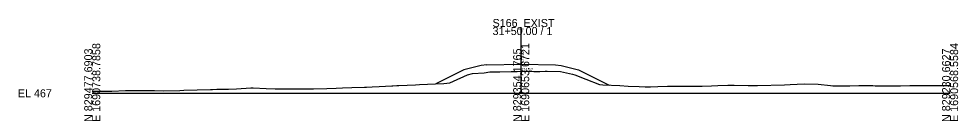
# Model space of a CAD drawing. Extents: x 1621104 to 1621433, y 1192880 to 1199414.
# Drawn here: x 1621104.2 to 1621432.7, y 1196879.5 to 1196915.2 of the extents above; entities that cross this region are included whole.
import ezdxf

# ---------------------------------------------------------------- set-up
doc = ezdxf.new("R2010")
doc.units = 0
for name, color, linetype in [('RD_GPK_XS_Cell', 7, 'Continuous'), ('RD_XS_EarthShd', 7, 'Continuous'), ('RD_XS_ExGround', 7, 'Continuous'), ('RD_XS_Pave', 7, 'Continuous'), ('RD_XS_TieSlope', 7, 'Continuous'), ('RD_XS_TX_Elev_EX', 7, 'Continuous'), ('RD_XS_TX_Elev_PR', 7, 'Continuous')]:
    doc.layers.add(name, color=color, linetype=linetype)

msp = doc.modelspace()

# ---------------------------------------------------------------- linework, layer by layer
at = {"layer": 'RD_GPK_XS_Cell'}
for p, q in [((1621279.86, 1196889.24), (1621279.86, 1196912.33)), ((1621129.86, 1196889.24), (1621279.86, 1196889.24)), ((1621279.86, 1196889.24), (1621429.86, 1196889.24))]:
    msp.add_line(p, q, dxfattribs=at)
at = {"layer": 'RD_XS_EarthShd'}
for p, q in [((1621267.86, 1196899.12), (1621265.86, 1196898.96)), ((1621291.86, 1196899.12), (1621293.86, 1196898.96))]:
    msp.add_line(p, q, dxfattribs=at)
at = {"layer": 'RD_XS_ExGround'}
msp.add_lwpolyline([(1621129.86, 1196890.01), (1621131.68, 1196889.97), (1621134.86, 1196889.97), (1621136.68, 1196890.04), (1621141.53, 1196890.17), (1621146.31, 1196890.19), (1621148.64, 1196890.17), (1621151.6, 1196890.17), (1621154.62, 1196890.09), (1621160.5, 1196890.27), (1621161.83, 1196890.35), (1621171.16, 1196890.6), (1621171.92, 1196890.62), (1621173.45, 1196890.65), (1621177.46, 1196890.7), (1621180.28, 1196890.84), (1621185.31, 1196891.14), (1621186.08, 1196891.15), (1621190.67, 1196890.87), (1621193.78, 1196890.82), (1621196.17, 1196890.81), (1621199.73, 1196890.75), (1621203.72, 1196890.8), (1621204.73, 1196890.82), (1621207.26, 1196890.82), (1621211.9, 1196890.92), (1621215.13, 1196890.98), (1621217.32, 1196891.14), (1621220.68, 1196891.24), (1621225.05, 1196891.36), (1621225.75, 1196891.4), (1621227.78, 1196891.47), (1621230.21, 1196891.56), (1621234.62, 1196891.83), (1621234.97, 1196891.85), (1621236.38, 1196891.9), (1621237.02, 1196891.94), (1621242.92, 1196892.18), (1621244.25, 1196892.26), (1621249.93, 1196892.55), (1621252.83, 1196892.69), (1621254.96, 1196892.84), (1621256.21, 1196893.49), (1621261.1, 1196895.65), (1621262.81, 1196896.11), (1621266.97, 1196896.34), (1621268.85, 1196896.66), (1621269.84, 1196896.71), (1621272.38, 1196896.72), (1621276.31, 1196896.85), (1621278.49, 1196896.88), (1621279.86, 1196896.9), (1621280.23, 1196896.91), (1621280.97, 1196896.91), (1621284.31, 1196896.86), (1621286.33, 1196896.89), (1621288.21, 1196896.93), (1621288.96, 1196896.92), (1621293.56, 1196896.89), (1621297.79, 1196895.89), (1621298.68, 1196895.66), (1621302.44, 1196894.16), (1621307.26, 1196892.26), (1621308.44, 1196892.17), (1621314.37, 1196891.93), (1621317.32, 1196891.74), (1621321.17, 1196891.62), (1621323.26, 1196891.55), (1621325.05, 1196891.49), (1621327.68, 1196891.6), (1621331.06, 1196891.74), (1621332.98, 1196891.76), (1621335.34, 1196891.68), (1621337.68, 1196891.72), (1621341.29, 1196891.77), (1621343.12, 1196891.74), (1621346.44, 1196891.8), (1621348.67, 1196891.96), (1621352.13, 1196892.13), (1621354.35, 1196892.08), (1621359.24, 1196891.92), (1621359.93, 1196891.9), (1621362.51, 1196891.99), (1621372, 1196892.19), (1621373.93, 1196892.26), (1621378.88, 1196892.54), (1621383.68, 1196892.44), (1621387.99, 1196891.91), (1621388.87, 1196891.87), (1621392.46, 1196891.84), (1621394.84, 1196891.79), (1621397.93, 1196891.9), (1621400.32, 1196891.98), (1621402.83, 1196891.91), (1621403.65, 1196891.87), (1621407.66, 1196891.88), (1621412.14, 1196891.87), (1621412.54, 1196891.86), (1621415.73, 1196891.93), (1621416.87, 1196891.96), (1621417.42, 1196891.95), (1621423.55, 1196891.92), (1621424.58, 1196891.93), (1621428, 1196891.93), (1621429.86, 1196891.93)], dxfattribs=at)
at = {"layer": 'RD_XS_Pave'}
for p, q in [((1621267.86, 1196899.12), (1621279.86, 1196899.36)), ((1621279.86, 1196899.36), (1621291.86, 1196899.12))]:
    msp.add_line(p, q, dxfattribs=at)
at = {"layer": 'RD_XS_TieSlope'}
for p, q in [((1621259.86, 1196897.46), (1621250.05, 1196892.56)), ((1621265.86, 1196898.96), (1621259.86, 1196897.46)), ((1621293.86, 1196898.96), (1621299.86, 1196897.46)), ((1621299.86, 1196897.46), (1621310.61, 1196892.08))]:
    msp.add_line(p, q, dxfattribs=at)

# ---------------------------------------------------------------- texts
at = {"layer": 'RD_GPK_XS_Cell'}
for s, p in [('S166_EXIST', (1621269.86, 1196912.33)), ('31+50.00 / 1', (1621269.86, 1196909.53)), ('EL 467', (1621103.86, 1196887.84))]:
    msp.add_text(s, height=2.8, dxfattribs=at).set_placement(p)
for s, p in [('N 829477.6903', (1621129.86, 1196879.24)), ('E 1690738.7858', (1621132.66, 1196879.24)), ('N 829354.1765', (1621279.86, 1196879.24)), ('E 1690653.6721', (1621282.66, 1196879.24)), ('N 829230.6627', (1621429.86, 1196879.24)), ('E 1690568.5584', (1621432.66, 1196879.24))]:
    msp.add_text(s, height=2.8, rotation=90, dxfattribs=at).set_placement(p)
at = {"layer": 'RD_XS_TX_Elev_EX'}
msp.add_text('474.67', height=1, dxfattribs=at).set_placement((1621279.76, 1196897))
at = {"layer": 'RD_XS_TX_Elev_PR'}
msp.add_text(' 477.12', height=1, rotation=90, dxfattribs=at).set_placement((1621280.86, 1196899.36))

doc.saveas('drawing.dxf')
